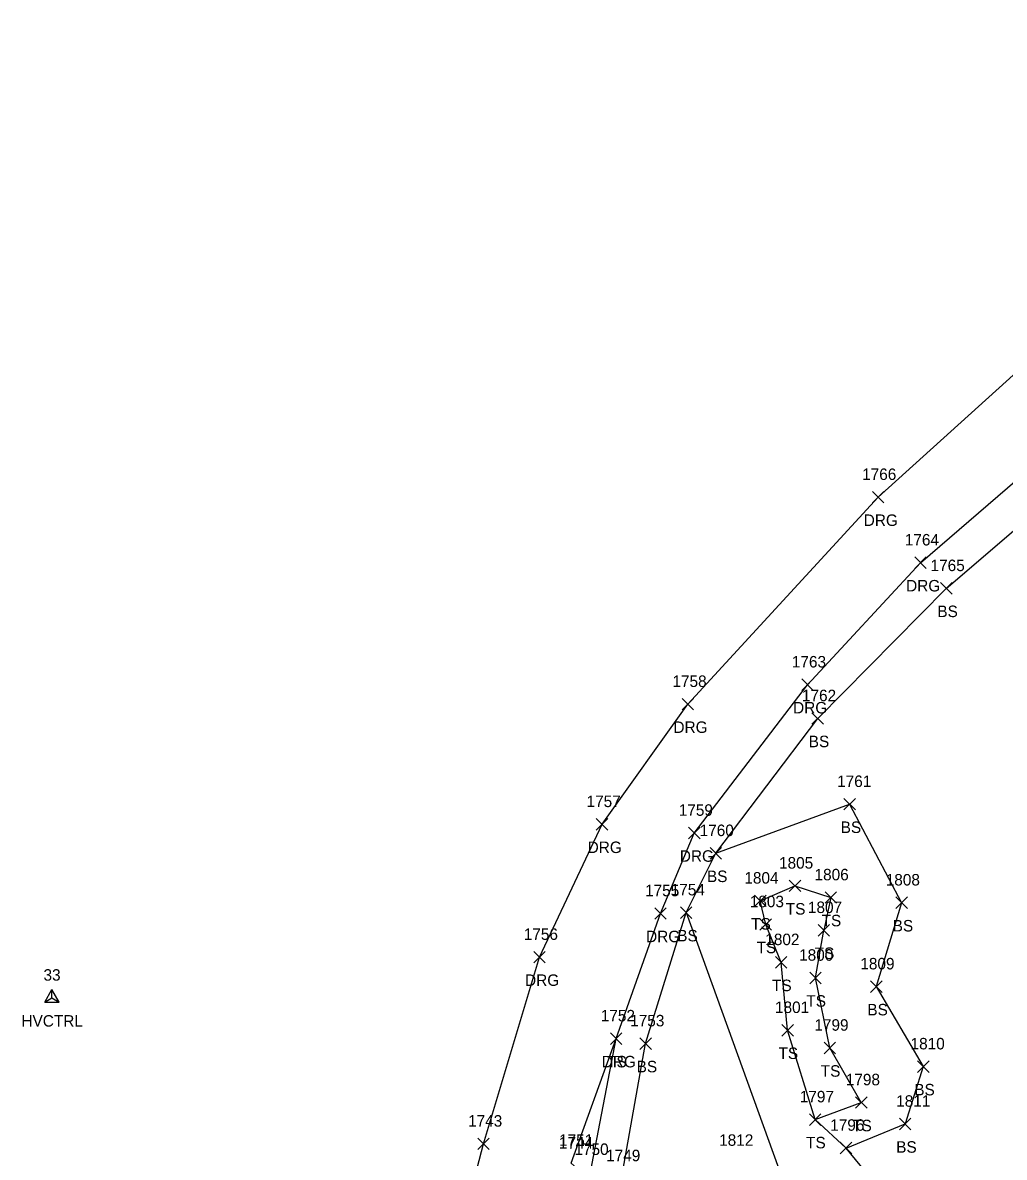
# Model space of a CAD drawing. Extents: x 1551995 to 1555700, y 777276 to 783130.
# Drawn here: x 1554684.9 to 1554855.8, y 778211.4 to 778408.8 of the extents above; entities that cross this region are included whole.
import ezdxf

# ---------------------------------------------------------------- set-up
doc = ezdxf.new("R2010")
doc.units = 0
for name, color, linetype in [('C_A', 7, 'Continuous'), ('C_I', 7, 'Continuous'), ('CPSM', 7, 'Continuous'), ('L_A', 7, 'Continuous'), ('L_I', 7, 'Continuous'), ('L_TIC', 7, 'Continuous'), ('LELB', 7, 'Continuous'), ('R_A', 7, 'Continuous'), ('R_I', 7, 'Continuous'), ('R_TIC', 7, 'Continuous'), ('RDG', 7, 'Continuous')]:
    doc.layers.add(name, color=color, linetype=linetype)

msp = doc.modelspace()

# ---------------------------------------------------------------- linework, layer by layer
at = {"layer": 'CPSM'}
for p, q in [((1554688.79, 778238.37), (1554690.04, 778240.54)), ((1554688.79, 778238.37), (1554690.04, 778239.09)), ((1554691.29, 778238.37), (1554690.04, 778240.54)), ((1554690.04, 778239.09), (1554690.04, 778240.54)), ((1554690.04, 778239.09), (1554690.04, 778239.09)), ((1554690.04, 778239.09), (1554691.29, 778238.37)), ((1554688.79, 778238.37), (1554691.29, 778238.37))]:
    msp.add_line(p, q, dxfattribs=at)
at = {"layer": 'L_TIC'}
for points in [[(1554844.67, 778309.36), (1554846.67, 778311.36)], [(1554846.67, 778309.36), (1554844.67, 778311.36)], [(1554822.29, 778286.72), (1554824.29, 778288.72)], [(1554824.29, 778286.72), (1554822.29, 778288.72)], [(1554827.85, 778271.79), (1554829.85, 778273.79)], [(1554829.85, 778271.79), (1554827.85, 778273.79)], [(1554804.57, 778263.25), (1554806.57, 778265.25)], [(1554806.57, 778263.25), (1554804.57, 778265.25)], [(1554804.57, 778263.25), (1554806.57, 778265.25)], [(1554806.57, 778263.25), (1554804.57, 778265.25)], [(1554818.33, 778257.59), (1554820.33, 778259.59)], [(1554820.33, 778257.59), (1554818.33, 778259.59)], [(1554812.3, 778254.98), (1554814.3, 778256.98)], [(1554814.3, 778254.98), (1554812.3, 778256.98)], [(1554824.57, 778255.55), (1554826.57, 778257.55)], [(1554826.57, 778255.55), (1554824.57, 778257.55)], [(1554799.41, 778252.93), (1554801.41, 778254.93)], [(1554801.41, 778252.93), (1554799.41, 778254.93)], [(1554799.41, 778252.93), (1554801.41, 778254.93)], [(1554801.41, 778252.93), (1554799.41, 778254.93)], [(1554836.9, 778254.65), (1554838.9, 778256.65)], [(1554838.9, 778254.65), (1554836.9, 778256.65)], [(1554813.24, 778250.87), (1554815.24, 778252.87)], [(1554815.24, 778250.87), (1554813.24, 778252.87)], [(1554823.36, 778249.86), (1554825.36, 778251.86)], [(1554825.36, 778249.86), (1554823.36, 778251.86)], [(1554823.36, 778249.86), (1554825.36, 778251.86)], [(1554825.36, 778249.86), (1554823.36, 778251.86)], [(1554815.94, 778244.27), (1554817.94, 778246.27)], [(1554817.94, 778244.27), (1554815.94, 778246.27)], [(1554821.91, 778241.56), (1554823.91, 778243.56)], [(1554823.91, 778241.56), (1554821.91, 778243.56)], [(1554832.49, 778240.05), (1554834.49, 778242.05)], [(1554834.49, 778240.05), (1554832.49, 778242.05)], [(1554817.06, 778232.46), (1554819.06, 778234.46)], [(1554819.06, 778232.46), (1554817.06, 778234.46)], [(1554787.23, 778231), (1554789.23, 778233)], [(1554789.23, 778231), (1554787.23, 778233)], [(1554792.35, 778230.14), (1554794.35, 778232.14)], [(1554794.35, 778230.14), (1554792.35, 778232.14)], [(1554824.41, 778229.38), (1554826.41, 778231.38)], [(1554826.41, 778229.38), (1554824.41, 778231.38)], [(1554840.66, 778226.13), (1554842.66, 778228.13)], [(1554842.66, 778226.13), (1554840.66, 778228.13)], [(1554829.88, 778219.88), (1554831.88, 778221.88)], [(1554831.88, 778219.88), (1554829.88, 778221.88)], [(1554821.86, 778216.91), (1554823.86, 778218.91)], [(1554823.86, 778216.91), (1554821.86, 778218.91)], [(1554821.86, 778216.91), (1554823.86, 778218.91)], [(1554823.86, 778216.91), (1554821.86, 778218.91)], [(1554837.5, 778216.15), (1554839.5, 778218.15)], [(1554839.5, 778216.15), (1554837.5, 778218.15)], [(1554837.5, 778216.15), (1554839.5, 778218.15)], [(1554839.5, 778216.15), (1554837.5, 778218.15)], [(1554827.22, 778211.97), (1554829.22, 778213.97)], [(1554829.22, 778211.97), (1554827.22, 778213.97)], [(1554827.22, 778211.97), (1554829.22, 778213.97)], [(1554829.22, 778211.97), (1554827.22, 778213.97)]]:
    msp.add_lwpolyline(points, dxfattribs=at)
at = {"layer": 'LELB'}
for points in [[(1554773.41, 778171.97), (1554778.92, 778183.17), (1554784.77, 778193.93), (1554789.2, 778196.75), (1554789.17, 778207.67), (1554793.35, 778231.14), (1554800.41, 778253.93), (1554805.57, 778264.25), (1554823.29, 778287.72), (1554845.67, 778310.36), (1554878.45, 778338.48), (1554911.83, 778363.48), (1554935.43, 778396.62)], [(1554888.1, 778278.07), (1554881.6, 778269.1), (1554881.41, 778246.04), (1554876.74, 778227.33), (1554877.84, 778223.95), (1554878.69, 778212.64), (1554860.35, 778200.47), (1554839.38, 778199.43), (1554828.22, 778212.97), (1554822.86, 778217.91), (1554830.88, 778220.88), (1554825.41, 778230.38), (1554822.91, 778242.56), (1554824.36, 778250.86)], [(1554805.57, 778264.25), (1554828.85, 778272.79), (1554837.9, 778255.65), (1554833.49, 778241.05), (1554841.66, 778227.13), (1554838.5, 778217.15)], [(1554822.86, 778217.91), (1554818.06, 778233.46), (1554816.94, 778245.27), (1554814.24, 778251.87), (1554813.3, 778255.98), (1554819.33, 778258.59), (1554825.57, 778256.55), (1554824.36, 778250.86)], [(1554800.41, 778253.93), (1554822.72, 778192.19), (1554838.05, 778187.79), (1554853.05, 778176.97), (1554852.09, 778152.19), (1554855.34, 778134.52), (1554846.3, 778116.53), (1554831.67, 778103.38), (1554813.35, 778099.28)], [(1554775.55, 778183.39), (1554783.46, 778194.4), (1554786.21, 778199.41), (1554783.74, 778208.76), (1554788.23, 778232)], [(1554828.22, 778212.97), (1554838.5, 778217.15)]]:
    msp.add_lwpolyline(points, dxfattribs=at)
at = {"layer": 'R_TIC'}
for points in [[(1554832.81, 778325.22), (1554834.81, 778327.22)], [(1554834.81, 778325.22), (1554832.81, 778327.22)], [(1554840.19, 778313.82), (1554842.19, 778315.82)], [(1554842.19, 778313.82), (1554840.19, 778315.82)], [(1554820.53, 778292.59), (1554822.53, 778294.59)], [(1554822.53, 778292.59), (1554820.53, 778294.59)], [(1554799.7, 778289.2), (1554801.7, 778291.2)], [(1554801.7, 778289.2), (1554799.7, 778291.2)], [(1554784.77, 778268.3), (1554786.77, 778270.3)], [(1554786.77, 778268.3), (1554784.77, 778270.3)], [(1554800.81, 778266.78), (1554802.81, 778268.78)], [(1554802.81, 778266.78), (1554800.81, 778268.78)], [(1554794.94, 778252.78), (1554796.94, 778254.78)], [(1554796.94, 778252.78), (1554794.94, 778254.78)], [(1554773.89, 778245.18), (1554775.89, 778247.18)], [(1554775.89, 778245.18), (1554773.89, 778247.18)], [(1554787.23, 778231), (1554789.23, 778233)], [(1554789.23, 778231), (1554787.23, 778233)], [(1554764.14, 778212.69), (1554766.14, 778214.69)], [(1554766.14, 778212.69), (1554764.14, 778214.69)]]:
    msp.add_lwpolyline(points, dxfattribs=at)
at = {"layer": 'RDG'}
for points in [[(1554731.76, 777736.57), (1554744.54, 777760.39), (1554749.58, 777791.25), (1554744.63, 777884.27), (1554742.18, 777937.77), (1554733.78, 777989.36), (1554731.62, 778029.74), (1554732.87, 778072.64), (1554738.87, 778112.72), (1554741.1, 778122.89), (1554752.14, 778165.58), (1554757.04, 778182.47), (1554765.14, 778213.69), (1554774.89, 778246.18), (1554785.77, 778269.3), (1554800.7, 778290.2), (1554833.81, 778326.22), (1554863.94, 778353.44), (1554894.55, 778381.82), (1554916.32, 778408.8)], [(1554765.41, 777786.83), (1554760.87, 777887.93), (1554755.21, 777940.6), (1554748.12, 777988.97), (1554746.63, 778028.6), (1554748.07, 778068.94), (1554755.05, 778099.35), (1554759.31, 778115.55), (1554764.29, 778135.87), (1554767.84, 778151.77), (1554770.94, 778162.89), (1554771.35, 778163.02), (1554773.41, 778171.97), (1554775.55, 778183.39), (1554780.94, 778209.88), (1554780.41, 778210.35), (1554788.23, 778232), (1554795.94, 778253.78), (1554801.81, 778267.78), (1554821.53, 778293.59), (1554841.19, 778314.82), (1554873.15, 778342.35), (1554907.49, 778367.57), (1554931.47, 778399.39)]]:
    msp.add_lwpolyline(points, dxfattribs=at)

# ---------------------------------------------------------------- texts
at = {"layer": 'C_A'}
msp.add_text('HVCTRL', height=2, dxfattribs=at).set_placement((1554684.73, 778234.09))
at = {"layer": 'C_I'}
msp.add_text('33', height=2, dxfattribs=at).set_placement((1554688.57, 778242.09))
at = {"layer": 'L_A'}
for s, p in [('BS', (1554844.11, 778305.36)), ('BS', (1554821.73, 778282.72)), ('BS', (1554827.29, 778267.79)), ('BS', (1554804.02, 778259.25)), ('BS', (1554804.02, 778259.25)), ('TS', (1554817.74, 778253.59)), ('TS', (1554811.71, 778250.98)), ('TS', (1554823.97, 778251.55)), ('BS', (1554798.85, 778248.93)), ('BS', (1554798.85, 778248.93)), ('BS', (1554836.34, 778250.65)), ('TS', (1554812.65, 778246.87)), ('TS', (1554822.77, 778245.86)), ('TS', (1554822.77, 778245.86)), ('TS', (1554815.35, 778240.27)), ('TS', (1554821.32, 778237.56)), ('BS', (1554831.93, 778236.05)), ('TS', (1554816.47, 778228.46)), ('TS', (1554786.64, 778227)), ('BS', (1554791.79, 778226.14)), ('TS', (1554823.82, 778225.38)), ('BS', (1554840.1, 778222.13)), ('TS', (1554829.29, 778215.88)), ('TS', (1554821.27, 778212.91)), ('TS', (1554821.27, 778212.91)), ('BS', (1554836.95, 778212.15)), ('BS', (1554836.95, 778212.15))]:
    msp.add_text(s, height=2, dxfattribs=at).set_placement(p)
at = {"layer": 'L_I'}
for s, p in [('1765', (1554842.93, 778313.36)), ('1762', (1554820.55, 778290.72)), ('1761', (1554826.67, 778275.79)), ('1760', (1554802.75, 778267.25)), ('1760', (1554802.75, 778267.25)), ('1805', (1554816.56, 778261.59)), ('1804', (1554810.53, 778258.98)), ('1806', (1554822.74, 778259.55)), ('1754', (1554797.71, 778256.93)), ('1754', (1554797.71, 778256.93)), ('1808', (1554835.13, 778258.65)), ('1803', (1554811.47, 778254.87)), ('1807', (1554821.59, 778253.86)), ('1807', (1554821.59, 778253.86)), ('1802', (1554814.17, 778248.27)), ('1800', (1554820.06, 778245.56)), ('1809', (1554830.71, 778244.05)), ('1801', (1554815.86, 778236.46)), ('1752', (1554785.54, 778235)), ('1753', (1554790.66, 778234.14)), ('1799', (1554822.71, 778233.38)), ('1810', (1554839.45, 778230.13)), ('1798', (1554828.18, 778223.88)), ('1797', (1554820.17, 778220.91)), ('1797', (1554820.17, 778220.91)), ('1811', (1554836.95, 778220.15)), ('1811', (1554836.95, 778220.15)), ('1796', (1554825.47, 778215.97)), ('1796', (1554825.47, 778215.97)), ('1812', (1554806.14, 778213.35)), ('1812', (1554806.14, 778213.35)), ('1750', (1554780.96, 778211.76)), ('1749', (1554786.47, 778210.67))]:
    msp.add_text(s, height=2, dxfattribs=at).set_placement(p)
at = {"layer": 'R_A'}
for p in [(1554831.3, 778321.22), (1554838.68, 778309.82), (1554819.01, 778288.59), (1554798.19, 778285.2), (1554783.26, 778264.3), (1554799.3, 778262.78), (1554793.43, 778248.78), (1554772.37, 778241.18), (1554785.72, 778227)]:
    msp.add_text('DRG', height=2, dxfattribs=at).set_placement(p)
at = {"layer": 'R_I'}
for s, p in [('1766', (1554831.02, 778329.22)), ('1764', (1554838.45, 778317.82)), ('1763', (1554818.79, 778296.59)), ('1758', (1554798.01, 778293.2)), ('1757', (1554783.07, 778272.3)), ('1759', (1554799.11, 778270.78)), ('1755', (1554793.25, 778256.78)), ('1756', (1554772.14, 778249.18)), ('1752', (1554785.54, 778235)), ('1743', (1554762.45, 778216.69)), ('1751', (1554778.28, 778213.35)), ('1744', (1554778.25, 778212.88))]:
    msp.add_text(s, height=2, dxfattribs=at).set_placement(p)

doc.saveas('drawing.dxf')
